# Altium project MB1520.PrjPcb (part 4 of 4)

## Sheet LCD.SchDoc: LCD
size A4; Date: Not used; ApprovedBy: Not used; CheckedBy: Not used; Author: Not used; CompanyName: STMicroelectronics; DrawnBy: Not used; Engineer: Not used; Organization: Not used; Address1: Not used; Address2: Not used; Address3: Not used; Address4: Not used; DocumentNumber: Not used; Revision: Not used; SheetNumber: 12; SheetTotal: 19
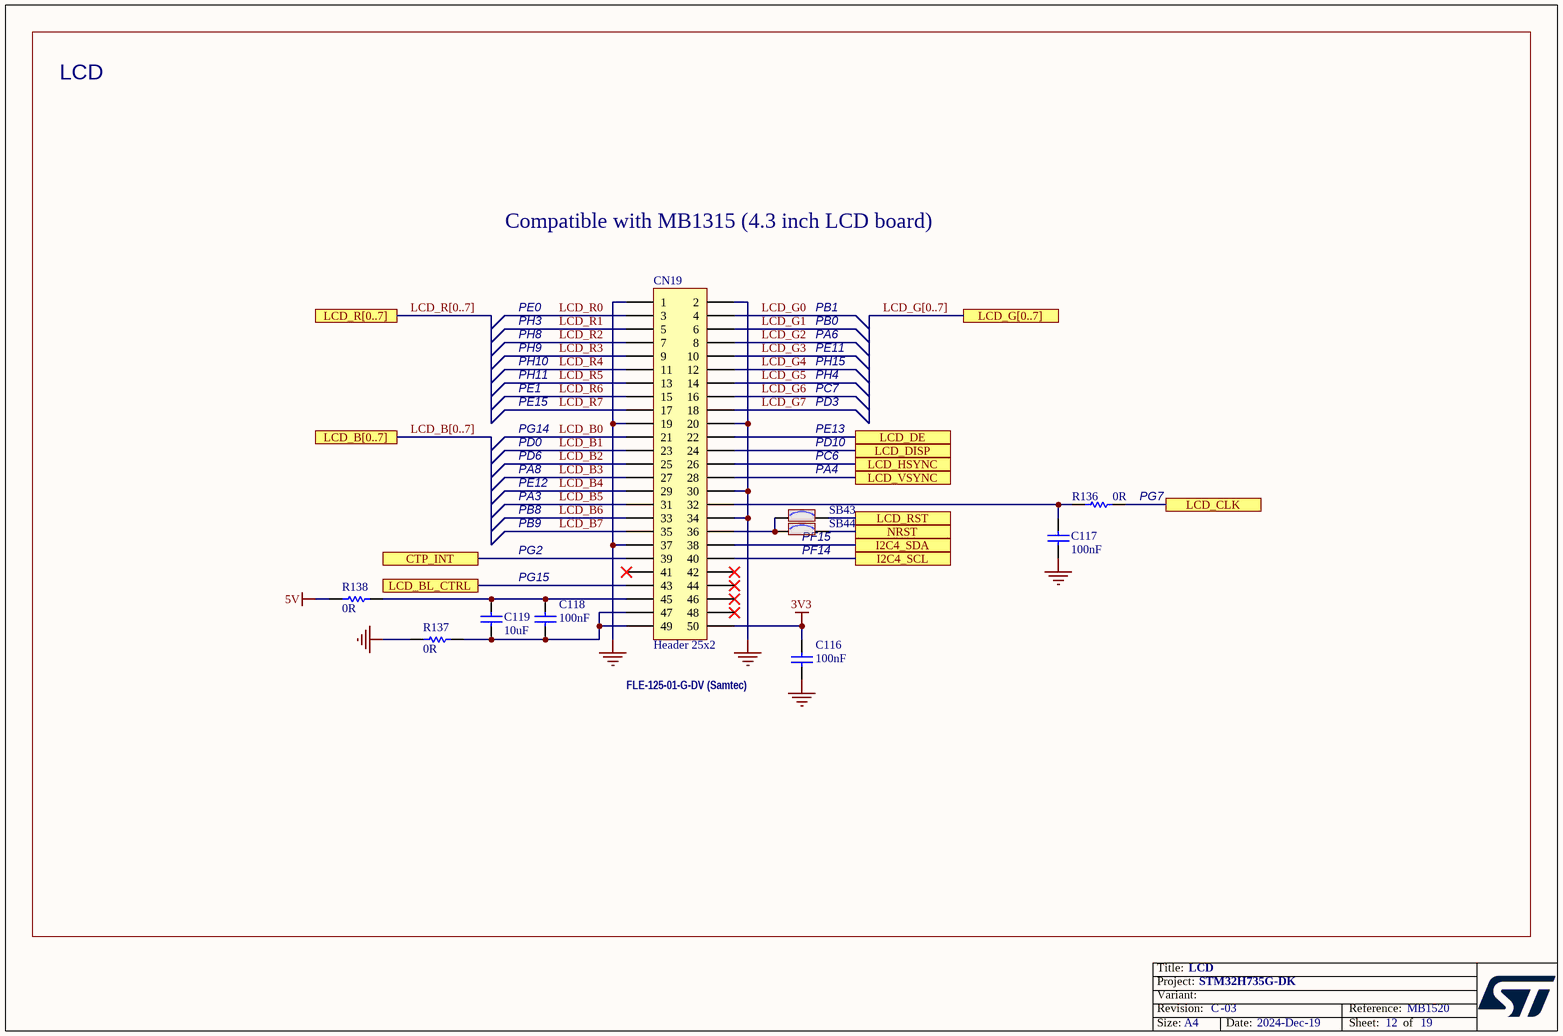
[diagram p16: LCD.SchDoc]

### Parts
C116  value 100nF  [C0402]  (hidden comment: Capacitor)
C117  value 100nF  [C0402]  (hidden comment: Capacitor)
C118  value 100nF  [C0402]  (hidden comment: Capacitor)
C119  value 10uF  [C0805]  (hidden comment: Capacitor)
CN19  Header 25x2  [MOD_LCD_MB1046B__CON_SAMTEC_FLE-125-01-G-DV]
R136  value 0R  [R0402]  (hidden comment: Resistor)
R137  value 0R  [R0603]  (hidden comment: Resistor)
R138  value 0R  [R0603]  (hidden comment: Resistor)
SB43  SB_ON  [SOLDER-BRIDGE_R0603-0R]  (value not drawn)
SB44  SB_ON  [SOLDER-BRIDGE_R0603-0R]  (value not drawn)

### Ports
CTP_INT, I2C4_SCL, I2C4_SDA, LCD_B[0..7], LCD_BL_CTRL, LCD_CLK, LCD_DE, LCD_DISP, LCD_G[0..7], LCD_HSYNC, LCD_R[0..7], LCD_RST, LCD_VSYNC, NRST

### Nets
3V3: C116.1 CN19.50
5V: R138.1
GND: C116.2 C117.1 CN19.1 CN19.2 CN19.19 CN19.20 CN19.30 CN19.34 CN19.37 R137.1  [project net POE7]
CTP_INT: CN19.39 ; port CTP_INT
I2C4_SCL: CN19.40 ; port I2C4_SCL
I2C4_SDA: CN19.38 ; port I2C4_SDA
LCD_B0: CN19.21
LCD_B1: CN19.23
LCD_B2: CN19.25
LCD_B3: CN19.27
LCD_B4: CN19.29
LCD_B5: CN19.31
LCD_B6: CN19.33
LCD_B7: CN19.35
LCD_BL_CTRL: CN19.43 ; port LCD_BL_CTRL
LCD_CLK: R136.2 ; port LCD_CLK
LCD_DE: CN19.22 ; port LCD_DE
LCD_DISP: CN19.24 ; port LCD_DISP
LCD_G0: CN19.4
LCD_G1: CN19.6
LCD_G2: CN19.8
LCD_G3: CN19.10
LCD_G4: CN19.12
LCD_G5: CN19.14
LCD_G6: CN19.16
LCD_G7: CN19.18
LCD_HSYNC: CN19.26 ; port LCD_HSYNC
LCD_R0: CN19.3
LCD_R1: CN19.5
LCD_R2: CN19.7
LCD_R3: CN19.9
LCD_R4: CN19.11
LCD_R5: CN19.13
LCD_R6: CN19.15
LCD_R7: CN19.17
LCD_RST: SB43.2 ; port LCD_RST
LCD_VSYNC: CN19.28 ; port LCD_VSYNC
RESET: SB44.2 ; port NRST
NetC117_2: C117.2 CN19.32 R136.1
NetC118_1: C118.1 C119.2 CN19.45 R138.2
NetC118_2: C118.2 C119.1 CN19.47 CN19.49 R137.2
NetCN19_36: CN19.36 SB43.1 SB44.1

Not connected (* = marked no-connect by the designer): CN19 41* 42* 44* 46* 48*

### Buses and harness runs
bus LCD_B[0..7] = port LCD_B[0..7]
bus LCD_G[0..7] = port LCD_G[0..7]
bus LCD_R[0..7] = port LCD_R[0..7]

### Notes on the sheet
- LCD
- Compatible with MB1315 (4.3 inch LCD board)
- PE0
- PB1
- PH3
- PH8
- PH9
- PH10
- PH11
- PA6
- PB0
- PE11
- PH15
- PH4
- PE1
- PD0
- PE15
- PG14
- PE13
- PD10
- PC7
- PD3
- PA3
- PA8
- PB8
- PD6
- PE12
- PA4
- PC6
- (near R136) PG7
- PG2
- PG15
- PB9
- (near SB44) PF15
- (near SB44) PF14
- (near C116) FLE-125-01-G-DV (Samtec)

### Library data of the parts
C116 C118 = MCD-00006: Capacitor, MLCC, 100nF, 16V, X7R, +/-10%, 0402, T=0.5mm; Manufacturer_Part_Number: CC0402KRX7R7BB104; Manufacturer: YAGEO; Part_Preference: Recommended; Partial_Alternate_Internal_Part_Number: MCD-03299; Component_Country_Of_Origin: China; ID: 2474; Order_Code_RS: 9402047; ShowFields: YES
C117 = MCD-00006: Capacitor, MLCC, 100nF, 16V, X7R, 10%, 0402, T=0.5mm; Manufacturer_Part_Number: CC0402KRX7R7BB104; Manufacturer: YAGEO; Part_Preference: Recommended; Partial_Alternate_Internal_Part_Number: MCD-03299; Provided_By: Subcon; Initial_Board_Reference: MB1274; Component_Country_Of_Origin: China; ID: 2474; Order_Code_RS: 616-9701; ShowFields: YES
C119 = MCD-00014: Capacitor, MLCC, 10uF, 25V, X5R, 10%, 0805, T=0,85mm; Manufacturer_Part_Number: CC0805KRX5R8BB106; Manufacturer: YAGEO; Full_Alternate_Internal_Part_Number: MCD-02385; Part_Preference: Recommended; Partial_Alternate_Internal_Part_Number: MCD-03053; Provided_By: Subcon; Initial_Board_Reference: MB1274; Component_Country_Of_Origin: China; ID: 2468; ShowFields: YES
CN19 = MCD-01222: Header 25x2 for MB1046 - LCD 4.3 inches daughter board; Part_Type: Connector; Manufacturer_Part_Number: FLE-125-01-G-DV; Manufacturer: SAMTEC; Part_Preference: Recommended; Provided_By: SUBCO; Initial_Board_Reference: MB1332; Component_Country_Of_Origin: China, Costa Rica, Malaysia, United States, Vietnam; ID: 3274; Order_Code_RS: 766-8965; ShowFields: YES
R136 = MCD-00052: Resistor,0R,0402,5%,1/16W; Manufacturer_Part_Number: RC0402JR-070RL; Manufacturer: YAGEO; Part_Preference: Recommended; ECCN_US: EAR99; ECCN_EU: NEC; Provided_By: SUBCO; Component_Country_Of_Origin: China; ID: 2540; Order_Code_RS: 618-5804; ShowFields: YES
R137 R138 = MCD-00056: Resistor,0R,0603,5%,1/10W; Manufacturer_Part_Number: RC0603JR-070RL; Manufacturer: YAGEO; Part_Preference: Recommended; Provided_By: subcon; Initial_Board_Reference: MB1274; Component_Country_Of_Origin: China; ID: 2536; ShowFields: YES
SB43 SB44 = MCD-00071: Solder Bridge ON; Part_Type: Misc; Manufacturer_Part_Number: RC0603JR-070RL; Manufacturer: YAGEO; Part_Preference: Recommended; Provided_By: SUBCO; ID: 2521; ShowFields: YES

## Sheet HyperRAM.SchDoc: HyperRAM
size A4; Date: Not used; ApprovedBy: Not used; CheckedBy: Not used; Author: Not used; CompanyName: STMicroelectronics; DrawnBy: Not used; Engineer: Not used; Organization: Not used; Address1: Not used; Address2: Not used; Address3: Not used; Address4: Not used; DocumentNumber: Not used; Revision: Not used; SheetNumber: 10; SheetTotal: 19
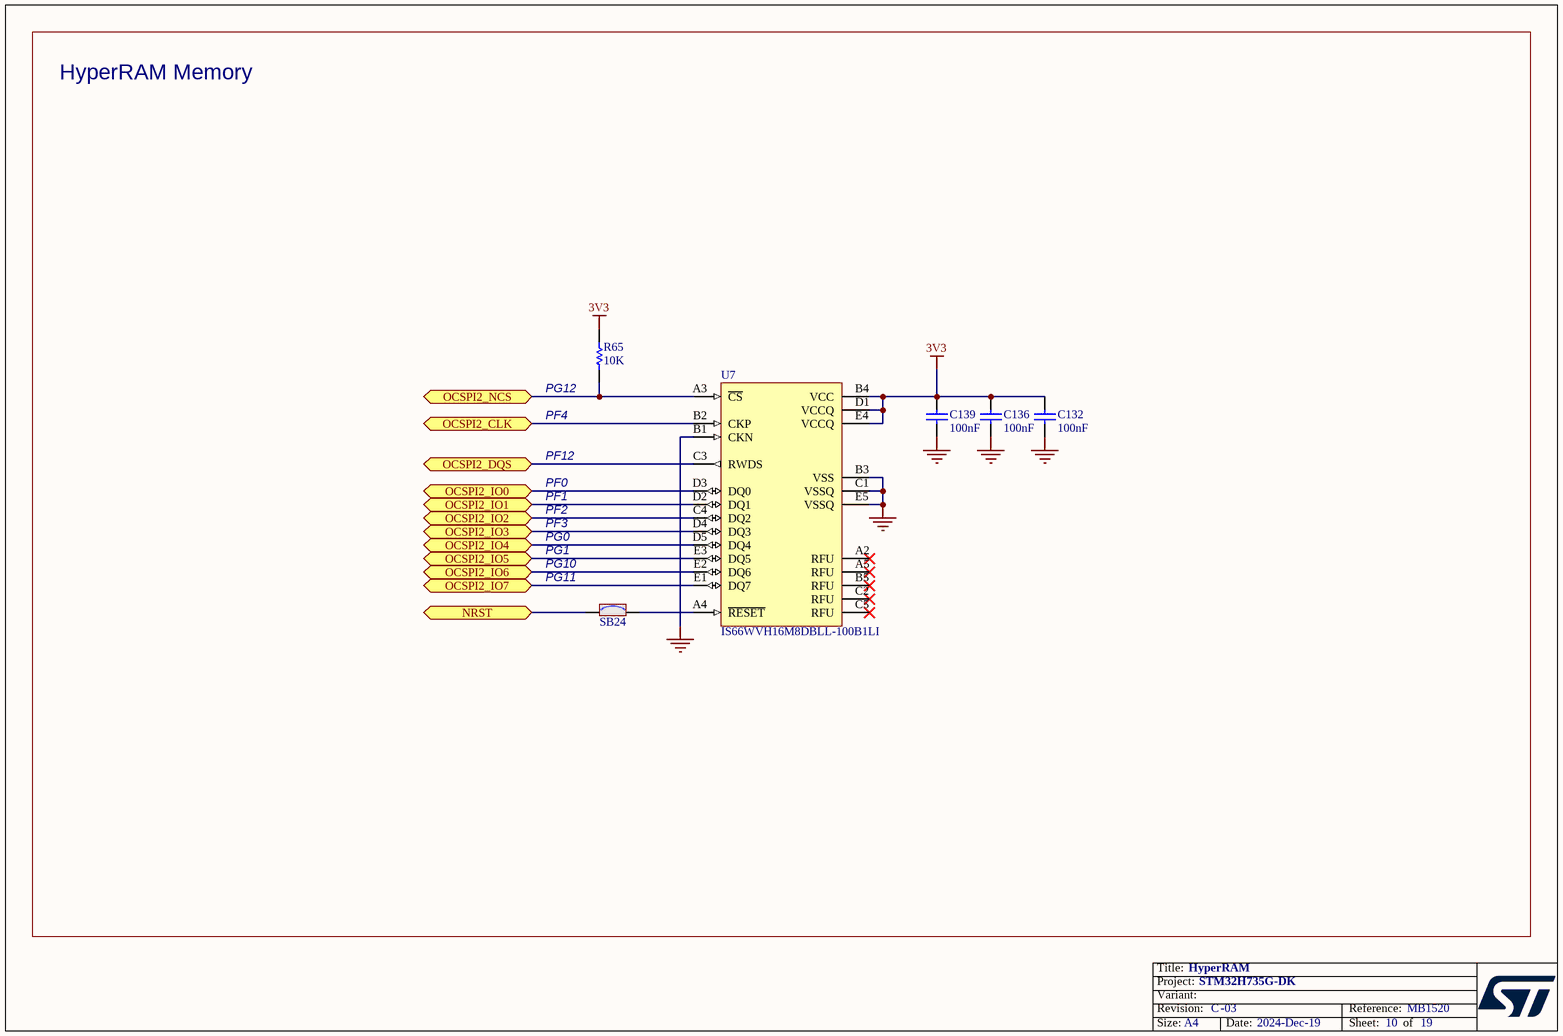
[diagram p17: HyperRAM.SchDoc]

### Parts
C132  value 100nF  [C0402]  (hidden comment: Capacitor)
C136  value 100nF  [C0402]  (hidden comment: Capacitor)
C139  value 100nF  [C0402]  (hidden comment: Capacitor)
R65  value 10K  [R0402]  (hidden comment: Resistor)
SB24  SB_ON  [SOLDER-BRIDGE_R0603-0R]  (value not drawn)
U7  value IS66WVH16M8DBLL-100B1LI  [ICC_FBGA24_5X5-BALL-ARRAY_6X8_P1]  (hidden comment: S70KL1281DABHI023)

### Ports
NRST (bidir), OCSPI2_CLK (bidir), OCSPI2_DQS (bidir), OCSPI2_IO0 (bidir), OCSPI2_IO1 (bidir), OCSPI2_IO2 (bidir), OCSPI2_IO3 (bidir), OCSPI2_IO4 (bidir), OCSPI2_IO5 (bidir), OCSPI2_IO6 (bidir), OCSPI2_IO7 (bidir), OCSPI2_NCS (bidir)

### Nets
3V3: C132.2 C136.2 C139.2 R65.2 U7.B4(VCC) U7.D1(VCCQ) U7.E4(VCCQ)
GND: C132.1 C136.1 C139.1 U7.B1(CKN) U7.B3(VSS) U7.C1(VSSQ) U7.E5(VSSQ)  [project net POE7]
OCSPI2_CLK: U7.B2(CKP) ; port OCSPI2_CLK
OCSPI2_DQS: U7.C3(RWDS) ; port OCSPI2_DQS
OCSPI2_IO0: U7.D3(DQ0) ; port OCSPI2_IO0
OCSPI2_IO1: U7.D2(DQ1) ; port OCSPI2_IO1
OCSPI2_IO2: U7.C4(DQ2) ; port OCSPI2_IO2
OCSPI2_IO3: U7.D4(DQ3) ; port OCSPI2_IO3
OCSPI2_IO4: U7.D5(DQ4) ; port OCSPI2_IO4
OCSPI2_IO5: U7.E3(DQ5) ; port OCSPI2_IO5
OCSPI2_IO6: U7.E2(DQ6) ; port OCSPI2_IO6
OCSPI2_IO7: U7.E1(DQ7) ; port OCSPI2_IO7
OCSPI2_NCS: R65.1 U7.A3(~{CS}) ; port OCSPI2_NCS
RESET: SB24.1 ; port NRST
NetSB24_2: SB24.2 U7.A4(~{RESET})

Not connected (* = marked no-connect by the designer): U7 A2(RFU)* A5(RFU)* B5(RFU)* C2(RFU)* C5(RFU)*

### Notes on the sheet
- HyperRAM Memory
- (near R65) PG12
- PF4
- PF12
- PF0
- PF1
- PF2
- PF3
- PG0
- PG1
- (near SB24) PG10
- (near SB24) PG11

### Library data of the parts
C132 C136 C139 = MCD-00006: as C116 on sheet LCD
R65 = MCD-00053: Resistor,10K,0402,1%,1/16W; Manufacturer_Part_Number: RC0402FR-0710KL; Manufacturer: YAGEO; BMS_Part_Number: 9131590; Part_Preference: Recommended; ECCN_US: EAR99; ECCN_EU: NEC; Provided_By: SUBCO; Component_Country_Of_Origin: China; ID: 2539; ShowFields: YES
SB24 = MCD-00071: as SB43 on sheet LCD
U7 = MCD-02091: Memory, HyperRAM,128Mb,100MHz,3V,BGA24; Part_Type: IC; Manufacturer: ISSI; Part_Preference: Recommended; Component_Country_Of_Origin: China, Taiwan; ID: 4191; ShowFields: YES

## Sheet SD_CARD.SchDoc: uSD CARD
size A4; Date: Not used; ApprovedBy: Not used; CheckedBy: Not used; Author: Not used; CompanyName: STMicroelectronics; DrawnBy: Not used; Engineer: Not used; Organization: Not used; Address1: Not used; Address2: Not used; Address3: Not used; Address4: Not used; DocumentNumber: Not used; Revision: Not used; SheetNumber: 11; SheetTotal: 19
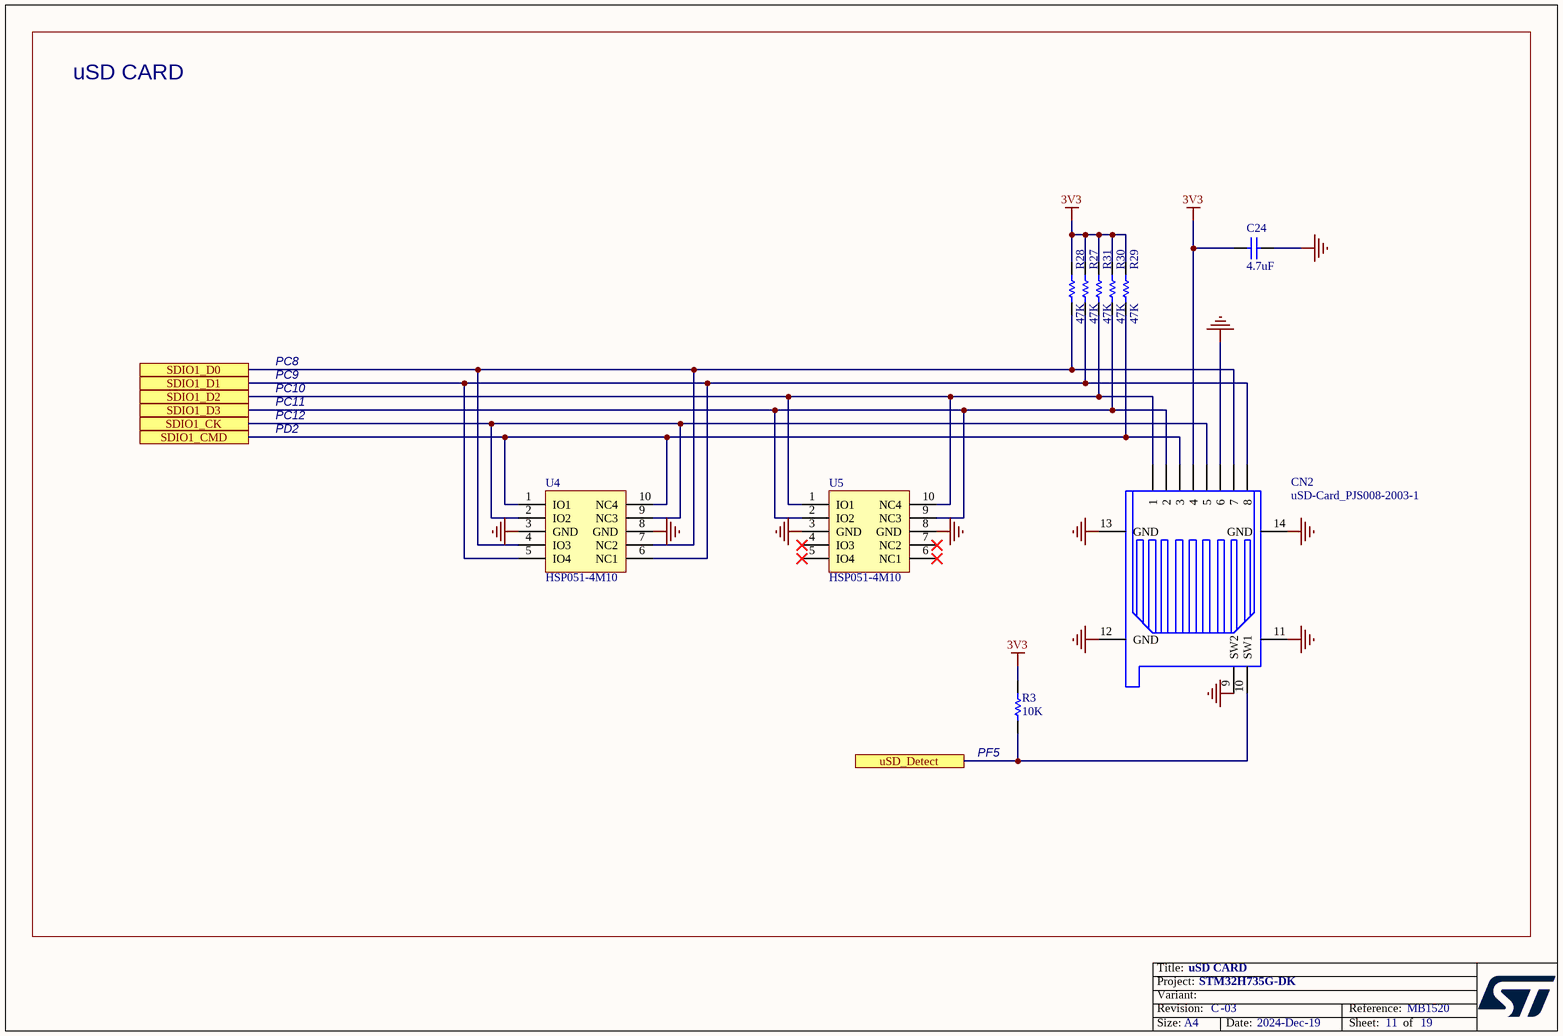
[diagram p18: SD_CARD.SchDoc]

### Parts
C24  value 4.7uF  [C0603_H0P8]  (hidden comment: Capacitor)
CN2  value uSD-Card_PJS008-2003-1  [CON_MICROSD_YAMAICHI_PJS008-2003-1]  (hidden comment: microSD-PJS008-2003)
R3  value 10K  [R0603]  (hidden comment: Resistor)
R27  value 47K  [R0402]  (hidden comment: Resistor)
R28  value 47K  [R0402]  (hidden comment: Resistor)
R29  value 47K  [R0402]  (hidden comment: Resistor)
R30  value 47K  [R0402]  (hidden comment: Resistor)
R31  value 47K  [R0402]  (hidden comment: Resistor)
U4  HSP051-4M10  [ESD_UQFN-10L_2P5X1_P050]
U5  HSP051-4M10  [ESD_UQFN-10L_2P5X1_P050]

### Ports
SDIO1_CK, SDIO1_CMD, SDIO1_D0, SDIO1_D1, SDIO1_D2, SDIO1_D3, uSD_Detect

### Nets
3V3: C24.1 CN2.4 R3.2 R27.2 R28.2 R29.2 R30.2 R31.2
GND: C24.2 CN2.6 CN2.9(SW2) CN2.11(GND) CN2.12(GND) CN2.13(GND) CN2.14(GND) U4.3(GND) U4.8(GND) U5.3(GND) U5.8(GND)  [project net POE7]
SDIO1_CK: CN2.5 U4.2(IO2) U4.9(NC3) ; port SDIO1_CK
SDIO1_CMD: CN2.3 R29.1 U4.1(IO1) U4.10(NC4) ; port SDIO1_CMD
SDIO1_D0: CN2.7 R28.1 U4.4(IO3) U4.7(NC2) ; port SDIO1_D0
SDIO1_D1: CN2.8 R27.1 U4.5(IO4) U4.6(NC1) ; port SDIO1_D1
SDIO1_D2: CN2.1 R31.1 U5.1(IO1) U5.10(NC4) ; port SDIO1_D2
SDIO1_D3: CN2.2 R30.1 U5.2(IO2) U5.9(NC3) ; port SDIO1_D3
uSD_Detect: CN2.10(SW1) R3.1 ; port uSD_Detect

Not connected (* = marked no-connect by the designer): U5 4(IO3)* 5(IO4)* 6(NC1)* 7(NC2)*

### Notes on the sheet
- uSD CARD
- PC8
- PC9
- PC10
- PC11
- PC12
- PD2
- (near R3) PF5

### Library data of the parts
C24 = MCD-01721: Capacitor, MLCC, 4.7uF, 10V, X5R, +/-10%, 0603, T=0.8mm; Manufacturer_Part_Number: CC0603KRX5R6BB475; Manufacturer: YAGEO; Part_Preference: Recommended; Component_Country_Of_Origin: China; ID: 3821; ShowFields: YES
CN2 = MCD-00023: MicroSD Card Conn, Reversed-Type, Mnt Push-Push, Positionning holes; Part_Type: Connector; Manufacturer_Part_Number: PJS008-2003-1; Manufacturer: YAMAICHI; Part_Preference: Recommended; Provided_By: SUBCO; Component_Country_Of_Origin: Unknown; ID: 2492; ShowFields: YES
R3 = MCD-00220: Resistor,10K,0603,1%,1/10W; Manufacturer_Part_Number: RC0603FR-0710KL; Manufacturer: YAGEO; Part_Preference: Recommended; ECCN_US: EAR99; ECCN_EU: NEC; Provided_By: SUBCO; Component_Country_Of_Origin: China; ID: 2649; ShowFields: YES
R27-R31 = MCD-00063: Resistor,47K,0402,1%,1/16W; Manufacturer_Part_Number: RC0402FR-0747KL; Manufacturer: YAGEO; Part_Preference: Recommended; Provided_By: SUBCO; Component_Country_Of_Origin: China; ID: 2528; ShowFields: YES
U4 U5 = MCD-00667: 4-line ESD protection for high speed lines; Part_Type: Diode; Manufacturer: STMICROELECTRONICS; BMS_Part_Number: 9179041; Manufacturer_HQ_COO: EU; Part_Preference: Recommended; ECCN_US: EAR99; ECCN_EU: NEC; Provided_By: SUBCO with ST control; Component_Country_Of_Origin: Philippines; ID: 3081; ShowFields: YES

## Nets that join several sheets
1V8: STM32_microcontroller_Power (C93.2 TP4.1 U14.5), Audio (6 pins)
3V3: STM32_microcontroller_Power (9 pins), TAG (CN21.1), Audio (13 pins), USB_OTG_FS (R117.2 R118.2 R132.2), Arduino_Connector (CN5.2 CN5.4 R145.2), STMod+ (9 pins), STM32_microcontroller_IOs (5 pins), Ethernet (8 pins), FDCAN (6 pins), STlink_V3E_Module (CN7.3 R112.2), OCSPI (8 pins), LCD (C116.1 CN19.50), HyperRAM (7 pins), SD_CARD (8 pins)
3V3_STLK: STlink_V3E_Module (6 pins), STlink_V3E_PWR (39 pins)
5V: STM32_microcontroller_Power (C107.2 U1.1 U1.2 U17.3), USB_OTG_FS (U24.5), Arduino_Connector (CN5.5), STMod+ (P2.6 P2.15), FDCAN (6 pins), STlink_V3E_Module (R107.1), STlink_V3E_PWR (6 pins), LCD (R138.1)
5V_POE: PoE (7 pins), STlink_V3E_PWR (D10.1 JP7.5)
5V_USB_CHGR: STlink_V3E_Module (C115.2 CN15.1 U30.1), STlink_V3E_PWR (6 pins)
E5V: STM32_microcontroller_Power (C94.2 U15.2 U15.4), Arduino_Connector (R72.1), STlink_V3E_PWR (D9.1 JP7.7)
POE7: STM32_microcontroller_Power (86 pins), TAG (CN21.3 CN21.5), Audio (36 pins), USB_OTG_FS (12 pins), Arduino_Connector (6 pins), STMod+ (8 pins), STM32_microcontroller_IOs (14 pins), Ethernet (16 pins), PoE (16 pins), FDCAN (15 pins), STlink_V3E_Module (28 pins), STlink_V3E_PWR (71 pins), HW_Mechanical_Parts (H1.1 H2.1 H3.1 H4.1), OCSPI (6 pins), LCD (10 pins), HyperRAM (7 pins), SD_CARD (11 pins)
USB_FS_VBUS: USB_OTG_FS (5 pins), STM32_microcontroller_IOs (U6.D13), STlink_V3E_PWR (D11.1 JP7.3)
VDD_ETH: Ethernet (SB9.2), PoE (C33.2 R42.2 T3.2)
VIN: STM32_microcontroller_Power (C97.2 U15.3), Arduino_Connector (CN5.8)
VREF+: STM32_microcontroller_Power (7 pins), Arduino_Connector (C49.2 SB23.2)
ARD_A0: Arduino_Connector (CN9.1), STM32_microcontroller_IOs (U6.L2)
ARD_A1: Arduino_Connector (CN9.2), STM32_microcontroller_IOs (U6.N4)
ARD_A2: Arduino_Connector (CN9.3), STM32_microcontroller_IOs (SB5.1)
ARD_A3: Arduino_Connector (CN9.4), STM32_microcontroller_IOs (U6.P3)
ARD_A4: Arduino_Connector (SB32.1), STM32_microcontroller_IOs (SB42.2)
ARD_A5: Arduino_Connector (SB33.1), STM32_microcontroller_IOs (U6.N2)
ARD_D0: Arduino_Connector (CN8.1), STM32_microcontroller_IOs (U6.K14)
ARD_D1: Arduino_Connector (CN8.2), STM32_microcontroller_IOs (U6.K15)
ARD_D2: Arduino_Connector (CN8.3), STM32_microcontroller_IOs (U6.H13)
ARD_D3: Arduino_Connector (CN8.4), STM32_microcontroller_IOs (U6.P1)
ARD_D4: Arduino_Connector (CN8.5), STM32_microcontroller_IOs (U6.G14)
ARD_D5: Arduino_Connector (CN8.6), STM32_microcontroller_IOs (U6.M12)
ARD_D6: Arduino_Connector (CN8.7), STM32_microcontroller_IOs (U6.J12)
ARD_D7: Arduino_Connector (CN8.8), STM32_microcontroller_IOs (U6.F15)
ARD_D8: Arduino_Connector (CN4.1), STM32_microcontroller_IOs (U6.B2)
ARD_D9: Arduino_Connector (CN4.2), STM32_microcontroller_IOs (U6.B5)
Audio_Int: Audio (U12.G3), STM32_microcontroller_IOs (U6.N8)
CTP_INT: STM32_microcontroller_IOs (U6.G15), LCD (CN19.39)
DETECTn: STMod+ (CN20.10), STM32_microcontroller_IOs (U6.A10)
FDCAN1_RX: STM32_microcontroller_IOs (U6.B12), FDCAN (U22.4)
FDCAN1_TX: STM32_microcontroller_IOs (U6.C13), FDCAN (U22.1)
FDCAN2_RX: STM32_microcontroller_IOs (U6.C6), FDCAN (U21.4)
FDCAN2_TX: STM32_microcontroller_IOs (U6.A5), FDCAN (U21.1)
FDCAN3_RX: STM32_microcontroller_IOs (SB29.1), FDCAN (U20.4)
FDCAN3_TX: STM32_microcontroller_IOs (SB30.1), FDCAN (U20.1)
I2C4_SCL: Audio (R90.1 U12.H1), LCD (CN19.40)
I2C4_SDA: Audio (R92.1 U12.F3), LCD (CN19.38)
LCD_B0: STM32_microcontroller_IOs (U6.C7), LCD (CN19.21)
LCD_B1: STM32_microcontroller_IOs (U6.C10), LCD (CN19.23)
LCD_B2: STM32_microcontroller_IOs (U6.D9), LCD (CN19.25)
LCD_B3: STM32_microcontroller_IOs (U6.B14), LCD (CN19.27)
LCD_B4: STM32_microcontroller_IOs (U6.P12), LCD (CN19.29)
LCD_B5: STM32_microcontroller_IOs (U6.N5), LCD (CN19.31)
LCD_B6: STM32_microcontroller_IOs (U6.A2), LCD (CN19.33)
LCD_B7: STM32_microcontroller_IOs (U6.B3), LCD (CN19.35)
LCD_BL_CTRL: STM32_microcontroller_IOs (U6.D7), LCD (CN19.43)
LCD_CLK: STM32_microcontroller_IOs (U6.G13), LCD (R136.2)
LCD_DE: STM32_microcontroller_IOs (U6.P13), LCD (CN19.22)
LCD_DISP: STM32_microcontroller_IOs (U6.L13), LCD (CN19.24)
LCD_G0: STM32_microcontroller_IOs (U6.M8), LCD (CN19.4)
LCD_G1: STM32_microcontroller_IOs (U6.R8), LCD (CN19.6)
LCD_G2: STM32_microcontroller_IOs (U6.R7), LCD (CN19.8)
LCD_G3: STM32_microcontroller_IOs (U6.R12), LCD (CN19.10)
LCD_G4: STM32_microcontroller_IOs (U6.D12), LCD (CN19.12)
LCD_G5: STM32_microcontroller_IOs (U6.P4), LCD (CN19.14)
LCD_G6: STM32_microcontroller_IOs (U6.D15), LCD (CN19.16)
LCD_G7: STM32_microcontroller_IOs (U6.A9), LCD (CN19.18)
LCD_HSYNC: STM32_microcontroller_IOs (U6.E14), LCD (CN19.26)
LCD_R0: STM32_microcontroller_IOs (U6.B4), LCD (CN19.3)
LCD_R1: STM32_microcontroller_IOs (U6.R4), LCD (CN19.5)
LCD_R2: STM32_microcontroller_IOs (U6.N13), LCD (CN19.7)
LCD_R3: STM32_microcontroller_IOs (U6.M14), LCD (CN19.9)
LCD_R4: STM32_microcontroller_IOs (U6.N14), LCD (CN19.11)
LCD_R5: STM32_microcontroller_IOs (U6.M13), LCD (CN19.13)
LCD_R6: STM32_microcontroller_IOs (U6.C4), LCD (CN19.15)
LCD_R7: STM32_microcontroller_IOs (U6.P14), LCD (CN19.17)
LCD_RST: STM32_microcontroller_IOs (U6.P15), LCD (SB43.2)
LCD_VSYNC: STM32_microcontroller_IOs (U6.P5), LCD (CN19.28)
MEMS_LED: STMod+ (CN20.12), STM32_microcontroller_IOs (U6.G12)
NJTRST: TAG (R150.1), STM32_microcontroller_IOs (U6.B6)
OCSPI1_CLK: STM32_microcontroller_IOs (R83.1), OCSPI (U10.B2)
OCSPI1_DQS: STM32_microcontroller_IOs (R101.1), OCSPI (U10.C3)
OCSPI1_IO0: STM32_microcontroller_IOs (R95.2), OCSPI (U10.D3)
OCSPI1_IO1: STM32_microcontroller_IOs (R91.2), OCSPI (U10.D2)
OCSPI1_IO2: STM32_microcontroller_IOs (R100.1), OCSPI (U10.C4)
OCSPI1_IO3: STM32_microcontroller_IOs (R98.2), OCSPI (U10.D4)
OCSPI1_IO4: STM32_microcontroller_IOs (R99.2), OCSPI (U10.D5)
OCSPI1_IO5: STM32_microcontroller_IOs (R96.2), OCSPI (U10.E3)
OCSPI1_IO6: STM32_microcontroller_IOs (R93.2), OCSPI (U10.E2)
OCSPI1_IO7: STM32_microcontroller_IOs (R87.2), OCSPI (U10.E1)
OCSPI1_NCS: STM32_microcontroller_IOs (R82.2), OCSPI (R81.1 U10.C2)
OCSPI2_CLK: STM32_microcontroller_IOs (R60.1), HyperRAM (U7.B2)
OCSPI2_DQS: STM32_microcontroller_IOs (R53.1), HyperRAM (U7.C3)
OCSPI2_IO0: STM32_microcontroller_IOs (R37.1), HyperRAM (U7.D3)
OCSPI2_IO1: STM32_microcontroller_IOs (R46.1), HyperRAM (U7.D2)
OCSPI2_IO2: STM32_microcontroller_IOs (R52.1), HyperRAM (U7.C4)
OCSPI2_IO3: STM32_microcontroller_IOs (R45.1), HyperRAM (U7.D4)
OCSPI2_IO4: STM32_microcontroller_IOs (R48.2), HyperRAM (U7.D5)
OCSPI2_IO5: STM32_microcontroller_IOs (R38.2), HyperRAM (U7.E3)
OCSPI2_IO6: STM32_microcontroller_IOs (R39.2), HyperRAM (U7.E2)
OCSPI2_IO7: STM32_microcontroller_IOs (R40.2), HyperRAM (U7.E1)
OCSPI2_NCS: STM32_microcontroller_IOs (R66.2), HyperRAM (R65.1 U7.A3)
OSC_25M: STM32_microcontroller_IOs (R35.1), Ethernet (R68.1)
PF6: STMod+ (SB10.1 SB17.1), STM32_microcontroller_IOs (SB29.2 U6.H1)
PF7: STMod+ (SB7.1 SB14.1), STM32_microcontroller_IOs (SB30.2 U6.J3)
PMOD11: STMod+ (P1.7 P2.11), STM32_microcontroller_IOs (U6.N15)
PMOD12: STMod+ (P1.8 P2.12), STM32_microcontroller_IOs (U6.K1)
PMOD17: STMod+ (CN20.6 P2.17), STM32_microcontroller_IOs (U6.P9)
PMOD18: STMod+ (CN20.3 CN20.4 P2.18), STM32_microcontroller_IOs (U6.R11)
PMOD19: STMod+ (CN20.5 P2.19), STM32_microcontroller_IOs (U6.R9)
PMOD20: STMod+ (CN20.7 P2.20), STM32_microcontroller_IOs (U6.N11)
RESET: TAG (R151.1), Arduino_Connector (CN5.3), STM32_microcontroller_IOs (5 pins), Ethernet (U9.15), STlink_V3E_Module (CN7.12 R108.1 U16.5), OCSPI (SB26.1), LCD (SB44.2), HyperRAM (SB24.1)
RMII_CRS_DV: STM32_microcontroller_IOs (U6.N6), Ethernet (R51.2 R56.1)
RMII_MDC: STM32_microcontroller_IOs (U6.L3), Ethernet (U9.13)
RMII_MDIO: STM32_microcontroller_IOs (U6.R2), Ethernet (R55.1 U9.12)
RMII_REF_CLK: STM32_microcontroller_IOs (U6.P2), Ethernet (R67.2 U9.14)
RMII_RX_ER: STM32_microcontroller_IOs (U6.N12), Ethernet (R57.1 U9.10)
RMII_RXD0: STM32_microcontroller_IOs (U6.R6), Ethernet (R49.1 R58.1)
RMII_RXD1: STM32_microcontroller_IOs (U6.M7), Ethernet (R50.1 R59.1)
RMII_TX_EN: STM32_microcontroller_IOs (R24.1), Ethernet (U9.16)
RMII_TXD0: STM32_microcontroller_IOs (R25.1), Ethernet (U9.17)
RMII_TXD1: STM32_microcontroller_IOs (R32.1), Ethernet (U9.18)
SAI1_SD_A: Audio (U12.F2), STM32_microcontroller_IOs (U6.E3)
SAI4_CK2: Audio (SB40.2), STM32_microcontroller_IOs (U6.D3)
SAI4_D2: Audio (SB39.2), STM32_microcontroller_IOs (U6.B1)
SDIO1_CK: STM32_microcontroller_IOs (U6.B11), SD_CARD (CN2.5 U4.2 U4.9)
SDIO1_CMD: STM32_microcontroller_IOs (U6.B10), SD_CARD (CN2.3 R29.1 U4.1 U4.10)
SDIO1_D0: STM32_microcontroller_IOs (U6.D14), SD_CARD (CN2.7 R28.1 U4.4 U4.7)
SDIO1_D1: STM32_microcontroller_IOs (U6.E13), SD_CARD (CN2.8 R27.1 U4.5 U4.6)
SDIO1_D2: STM32_microcontroller_IOs (U6.C12), SD_CARD (CN2.1 R31.1 U5.1 U5.10)
SDIO1_D3: STM32_microcontroller_IOs (U6.C11), SD_CARD (CN2.2 R30.1 U5.2 U5.9)
STMOD#3: STMod+ (SB6.1 SB8.1), STM32_microcontroller_IOs (U6.J2)
STMOD#4: STMod+ (SB12.1 SB15.1), STM32_microcontroller_IOs (U6.J4)
STMOD#7-SCL: STMod+ (P2.7), STM32_microcontroller_IOs (U6.R10)
STMOD#8-MOSIs: STMod+ (P2.8), STM32_microcontroller_IOs (U6.N7)
STMOD#9-MISOs: STMod+ (P2.9), STM32_microcontroller_IOs (U6.M11)
STMOD#10-SDA: STMod+ (P2.10), STM32_microcontroller_IOs (U6.N10)
STMOD#13-ADC: STMod+ (P2.13), STM32_microcontroller_IOs (U6.P6)
STMOD#14-PWM: STMod+ (P2.14), STM32_microcontroller_IOs (U6.H14)
T_JTDI: TAG (R148.1), STM32_microcontroller_IOs (U6.A11), STlink_V3E_Module (CN7.10 U34.1)
T_PWR_EN: STlink_V3E_Module (U13.R5), STlink_V3E_PWR (R127.1 U23.4)
T_SWCLK: TAG (R153.1), STM32_microcontroller_IOs (U6.A12), STlink_V3E_Module (CN7.6 JP2.1 R104.1 U16.3)
T_SWDIO: TAG (R152.1), STM32_microcontroller_IOs (U6.B13), STlink_V3E_Module (CN7.4 JP2.2 R103.1 U16.4)
T_SWO: TAG (R147.1), STM32_microcontroller_IOs (U6.A6), STlink_V3E_Module (CN7.8 R106.1 U16.1)
T_VCP_RX: STM32_microcontroller_IOs (U6.K13), STlink_V3E_Module (CN7.13 R114.2 U18.1)
T_VCP_TX: STM32_microcontroller_IOs (U6.L14), STlink_V3E_Module (CN7.14 R110.1 U18.3)
USB_FS_DM: USB_OTG_FS (CN14.2 U25.3), STM32_microcontroller_IOs (U6.C15)
USB_FS_DP: USB_OTG_FS (CN14.3 U25.4), STM32_microcontroller_IOs (U6.B15)
USB_FS_ID: USB_OTG_FS (CN14.4 U25.6), STM32_microcontroller_IOs (U6.C14)
USB_FS_OVCR: USB_OTG_FS (R116.2), STM32_microcontroller_IOs (U6.B7)
USB_FS_PWR_EN: USB_OTG_FS (R128.1), STM32_microcontroller_IOs (U6.R5)
uSD_Detect: STM32_microcontroller_IOs (U6.H3), SD_CARD (CN2.10 R3.1)
USER_LED1: STMod+ (R144.1), STM32_microcontroller_IOs (U6.M2)
USER_LED2: STMod+ (R143.1), STM32_microcontroller_IOs (U6.M1)
WAKEUP: STMod+ (R141.2), STM32_microcontroller_IOs (U6.C1)

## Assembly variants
H725I: not fitted C14 C21 C26 C44 C47 C49 C72 C117 C138 CN6 CN21 JP2 R3 R5 R16 R64 R70 R94 SB1 SB3 SB4 SB6 SB10 SB14 SB15 SB16 SB18 SB19 SB23 SB27 SB28 SB29 SB30 SB31 SB34 SB35 SB37 SB38 T1 U1
H735I: not fitted C14 C21 C26 C44 C47 C49 C72 C117 C138 CN6 CN21 JP2 R3 R5 R16 R64 R70 R94 SB1 SB3 SB4 SB7 SB8 SB12 SB16 SB17 SB18 SB19 SB23 SB27 SB28 SB29 SB30 SB31 SB34 SB35 SB37 SB38 SB44 T1 U1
